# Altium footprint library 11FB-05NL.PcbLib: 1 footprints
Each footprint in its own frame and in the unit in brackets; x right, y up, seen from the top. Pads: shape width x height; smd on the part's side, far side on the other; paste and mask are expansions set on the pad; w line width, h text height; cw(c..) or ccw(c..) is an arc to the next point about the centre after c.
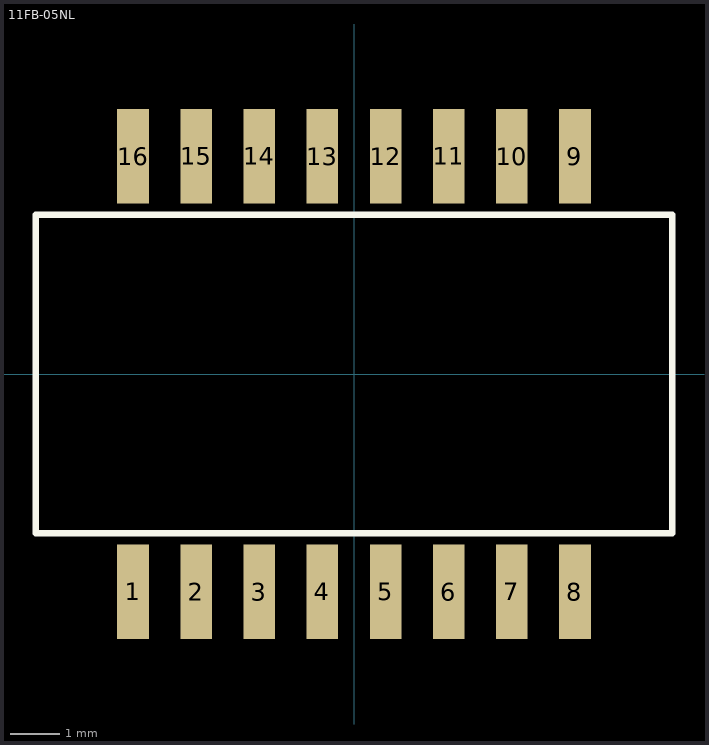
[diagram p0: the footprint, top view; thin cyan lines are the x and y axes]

## 11FB-05NL [mm] "11FB-05NL"
pads (16):
  rect 0.635x1.91 smd: 1(-4.445,-4.38) 2(-3.175,-4.38) 3(-1.905,-4.38) 4(-0.635,-4.38) 5(0.635,-4.38) 6(1.905,-4.38) 7(3.175,-4.38) 8(4.445,-4.38) 9(4.445,4.38) 10(3.175,4.38) 11(1.905,4.38) 12(0.635,4.38) 13(-0.635,4.38) 14(-1.905,4.38) 15(-3.175,4.38) 16(-4.445,4.38)
Top Overlay:
  lines w0.127: -6.4,-3.2 -6.4,3.2 6.4,3.2 6.4,-3.2 -6.4,-3.2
